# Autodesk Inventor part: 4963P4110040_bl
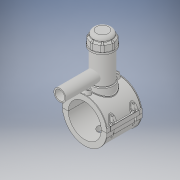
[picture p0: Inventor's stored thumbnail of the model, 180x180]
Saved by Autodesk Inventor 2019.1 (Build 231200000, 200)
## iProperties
Created: 2017-07
Part Number: 4963P4110040_bl
Material: Generic
Document SubType Name: Modeling
Designer: KIM
Density: 1 g/cm^3
Appearance: Default
Author: KIM
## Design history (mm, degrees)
derived "4963P4.ipt"
feature "Solid1::4963P4.ipt" dims "ScaleForDerivedMember" = 10
feature "Solid2::4963P4.ipt" dims "ScaleForDerivedMember" = 10
feature "Solid3::4963P4.ipt" dims "ScaleForDerivedMember" = 10
tag "TaggingFeature1"
body "Solid1"
body "Solid2"
body "Solid3"
other parameters: "d2" = 148 [user parameter], "d3" = 27.5 [user parameter], "d4" = 118 [user parameter], "d5" = 0 [user parameter], "d6" = 0.1 [user parameter], "d8" = 0 [user parameter], "d19" = 6 [user parameter], "d20" = 6 [user parameter], "d21" = 70.8 [user parameter], "d23" = 0 [user parameter], "d24" = 35.4 [user parameter], "d26" = 0 [user parameter], "d27" = 3 [user parameter], "d28" = 3 [user parameter], "d29" = 3 [user parameter], "d30" = 36.66667 [user parameter], "d31" = 6 [user parameter], "d32" = 0 [user parameter], "d33" = 0 [user parameter], "d34" = 0.6 [user parameter], "d40" = 74.36 [user parameter], "d41" = 77 [user parameter], "d43" = 0 [user parameter], "d45" = 0 [user parameter], "d47" = 142.3 [user parameter], "d70" = 15 [user parameter], "d72" = 0 [user parameter], "d73" = 6 [user parameter], "d75" = 5 [user parameter], "d76" = 0 [user parameter], "d77" = 5.5 [user parameter], "d78" = 85 [user parameter], "d79" = 15 [user parameter], "d80" = 47.2 [user parameter], "d82" = 5 deg [user parameter], "d84" = 4 [user parameter], "d85" = 14 [user parameter], "d86" = 0 [user parameter], "d87" = 3 [user parameter], "d88" = 0 [user parameter], "d89" = 1 [user parameter], "d90" = 1 [user parameter], "d91" = 94.4 [user parameter], "d92" = 0 [user parameter], "d93" = 0.5 [user parameter], "d94" = 57.89474 [user parameter], "d96" = 145.86 [user parameter], "d97" = 2.36 [user parameter], "d98" = 0 [user parameter], "d102" = 1.1 [user parameter], "d120" = 140 deg [user parameter], "d121" = 24.228 [user parameter], "d122" = 20 deg [user parameter], "d123" = 286 [user parameter], "d124" = 85.8 [user parameter], "d126" = 0 [user parameter], "d143" = 113.3 [user parameter], "d145" = 25.38462 [user parameter], "d149" = 1.65 [user parameter], "d150" = 27.92308 [user parameter], "d153" = 118 [user parameter], "d154" = 0 [user parameter], "d156" = 71.5 [user parameter], "d157" = 160 deg [user parameter], "d159" = 6.6 [user parameter], "d161" = 1.65 [user parameter], "d162" = 70.8 [user parameter], "d163" = 0 [user parameter], "d164" = 55 [user parameter], "d167" = 11 [user parameter], "d168" = 69.7561 [user parameter], "d170" = 3.75 [user parameter], "d172" = 0 [user parameter], "d173" = 1 [user parameter], "d175" = 55 [user parameter], "d176" = 20 deg [user parameter], "d177" = 7.7 [user parameter], "d178" = 33 [user parameter], "d180" = 0 [user parameter], "d183" = 13.2 [user parameter], "d184" = 6.16 [user parameter], "d185" = 38.35 [user parameter], "d186" = 38.35 [user parameter], "d187" = 71.5 [user parameter], "d188" = 9.9 [user parameter], "d189" = 7.7 [user parameter], "d190" = 0 [user parameter], "d191" = 107.25 [user parameter], "d193" = 8 [user parameter], "d194" = 4.13 [user parameter], "d195" = 90 deg [user parameter], "d197" = 0 [user parameter], "d199" = 0 [user parameter], "d200" = 16.5 [user parameter], "d202" = 0 [user parameter], "d203" = 177 [user parameter], "d204" = 73.15 [user parameter], "d205" = 53.9 [user parameter], "d206" = 65.45 [user parameter], "d207" = 132.75 [user parameter], "d208" = 138.06 [user parameter], "d209" = 164.61 [user parameter], "d210" = 66.22 [user parameter], "d211" = 77 [user parameter], "d212" = 61.6 [user parameter], "d213" = 36 [user parameter], "d216" = 0 [user parameter], "d217" = 11 [user parameter], "d218" = 11 [user parameter], "d219" = 2.2 [user parameter], "d224" = 0 [user parameter], "d227" = 32 [user parameter], "d228" = 142 [user parameter], "d230" = 6.6 [user parameter], "B_" = 148 [user parameter], "L_" = 118 [user parameter], "d_t" = 6 [user parameter], "H_2" = 177 [user parameter], "H_" = 142 [user parameter], "d1" = 143 [user parameter]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
